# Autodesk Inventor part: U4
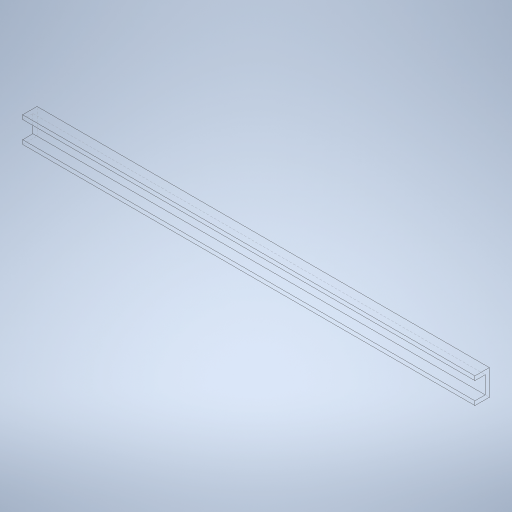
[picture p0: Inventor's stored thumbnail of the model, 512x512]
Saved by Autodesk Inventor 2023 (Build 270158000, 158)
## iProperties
Created: 2023-11
Part Number: U4
Material: Generic
Document SubType Name: Modeling
Designer: tornqvih
Density: 1 g/cm^3
Appearance: Default
Author: tornqvih
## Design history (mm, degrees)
sketch "Sketch1"
  geometry: L1 (6.25, 2.5)-(6.25, -4.5); L2 (6.25, -4.5)-(-6.25, -4.5); L3 (-6.25, -4.5)-(-6.25, 2.5); L4 (-6.25, 2.5)-(-4.25, 2.5); L5 (-4.25, 2.5)-(-4.25, -2.5); L6 (-4.25, -2.5)-(4.25, -2.5); L7 (4.25, -2.5)-(4.25, 2.5); L8 (4.25, 2.5)-(6.25, 2.5); L9 (0, -5.9)-(0, 3.9) reference; L10 (-8.75, 0)-(8.75, 0) reference; 1 further point
  constraints: 16 end point, 5 symmetric about line, 2 vertical, 1 horizontal alignment, 1 point on line
  dimensions: "d0" = 5 distance of L6.end L7.end; "d1" = 2 distance between parallel lines of L1 L7; "d2" = 2 distance between parallel lines of L2 L6; "d3" = 8.5 distance of L5.end L6.end
extrude "Extrusion1" new body sketch "Sketch1" distance "d4" = 220; taper "d5" = 0 deg
body "Solid1"
